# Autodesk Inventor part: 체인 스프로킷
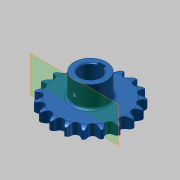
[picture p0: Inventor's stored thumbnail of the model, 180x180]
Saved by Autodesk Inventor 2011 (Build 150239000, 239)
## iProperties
Created: 2014-11
Part Number: 체인 스프로킷
Material: Steel
Document SubType Name: Modeling
Designer: KYOUNG IL JANG
Density: 7.85 g/cm^3
Mass: 738.264 g
Surface Area: 236.923 cm^2
Volume: 94.0463 cm^3
CustomPartVersion: 1
Company: 한국ATC센터
Author: KYOUNG IL JANG
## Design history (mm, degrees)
sketch "이론적 톱니 프로파일"
  geometry: L1 (0, 0)-(0, 45.567); L2 (0, 0)-(14.795, 43.098); L3 (0, 45.567)-(14.795, 43.098); L4 (0, 45.567)-(5.661, 50.015); L5 (5.661, 50.015)-(-5.141, 45.406); L6 (-12.428, 43.493)-(-5.573, 46.417); L7 (-5.141, 45.406)-(-5.573, 46.417); L8 (5.573, 46.417)-(5.141, 45.406); L9 (0, 0)-(8.138, 48.771); A1 r 45.567 centre (0, 0) between (0, 45.567) and (14.795, 43.098); A2 r 49.445 centre (0, 0) between (7.302, 48.903) and (-7.302, 48.903); A3 r 4.545 centre (0, 45.567) between (-3.574, 42.758) and (3.574, 42.758); A4 r 7.453 centre (12.428, 43.493) between (7.302, 48.903) and (5.573, 46.417); A5 r 7.453 centre (-12.428, 43.493) between (-5.573, 46.417) and (-7.302, 48.903); A6 r 11.745 centre (5.661, 50.015) between (-5.141, 45.406) and (-3.574, 42.758); A7 r 11.745 centre (-5.661, 50.015) between (3.574, 42.758) and (5.141, 45.406); 2 further points
  constraints: 18 end point, 15 point on circle, 7 centre point, 3 coincident, 3 point on line, 3 symmetric about line, 3 tangent, 1 equal radius, 1 midpoint, 1 parallel, 1 vertical, 1 other
  dimensions: "d0" = 91.13301 diameter of A1 (computed from da_p, da_z); "d2" = 18.9474 deg angle of L2 L1 (computed from da_z); "d3" = 4.545 radius of A3 (= 0.5 x da_Dr + da_SC); "d10" = 128.158 deg angle of L4 L1 (computed from da_z); "d11" = 15.0526 deg angle of L5 L4 (computed from da_z); "d12" = 7.2 distance of L3.start L4.end (= 0.8 x da_Dr); "d13" = 11.745 distance of L4.end L5.end (= 1.3 x da_Dr + da_SC); "d14" = 12.6 distance of A4.centre L1.end (= 1.4 x da_Dr); "d23" = 4.5 distance from line of L9.end L3 (= da_Ha)
sketch "톱니 프로파일"
  geometry: L1 (0, 0)-(0, 45.567); L2 (0, 45.567)-(4.203, 43.837); L3 (0, 45.567)-(-4.203, 43.837); A1 r 4.545 centre (0, 45.567) between (-4.203, 43.837) and (4.203, 43.837); A2 r 22.68 centre (25.176, 35.206) between (7.12, 48.93) and (4.203, 43.837); A3 r 22.68 centre (-25.176, 35.206) between (-4.203, 43.837) and (-7.12, 48.93); A4 r 49.445 centre (0, 0) between (-7.12, 48.93) and (7.12, 48.93) reference; 1 further point
  constraints: 9 point on circle, 6 end point, 3 centre point, 2 tangent, 1 coincident, 1 equal radius, 1 vertical, 1 other
  dimensions: "d44" = 135.263 deg angle of L3 L2 (= da_Alfa); "d45" = 22.68 radius of A2 (= da_Re); "d46" = 4.545 radius of A1 (= da_Ri)
sketch "단면 프로파일"
  geometry: L1 (49.445, 0)-(-49.445, 0) reference; L2 (33.265, 6.65)-(-33.265, 6.65); L3 (-33.265, 6.65)-(-33.265, -6.65); L4 (-33.265, -6.65)-(33.265, -6.65); L5 (33.265, -6.65)-(33.265, 6.65); L6 (33.265, 6.65)-(49.445, 6.65); L7 (49.445, 6.65)-(49.445, -6.65); L8 (49.445, -6.65)-(33.265, -6.65); L9 (33.265, -6.65)-(33.265, 6.65); L10 (42.183, 6.65)-(0, 6.65); L11 (0, 6.65)-(0, -6.65); L12 (0, -6.65)-(42.183, -6.65); L13 (0, 6.65)-(0, -6.65); L14 (49.445, 4.775)-(49.445, -4.775); A1 r 15 centre (42.183, -8.35) between (49.445, 4.775) and (42.183, 6.65); A2 r 15 centre (42.183, 8.35) between (42.183, -6.65) and (49.445, -4.775); 2 further points
  constraints: 26 end point, 7 midpoint, 5 perpendicular, 4 parallel, 4 point on circle, 3 point on line, 3 symmetric about line, 2 centre point, 2 horizontal, 2 tangent, 1 collinear, 1 other
  dimensions: "d30" = 13.3 distance between parallel lines of L8 L6 (= da_Bf); "d31" = 66.53007 distance between parallel lines of L3 L5 (= da_Ds); "d32" = 13.3 distance between parallel lines of L4 L2 (= da_Bs); "d33" = 1.875 distance from line of L14.start L6 (= da_Ba); "d34" = 15 radius of A1 (= da_Rx); "d43" = 6.65 distance between parallel lines of L4 L1 (computed from da_k, da_pt, da_Bs)
revolve "슈라우드" stored, may be unused: angle "d36" = 90 deg
revolve "스트랜드" stored, may be unused: angle "d37" = 90 deg
extrude "이론적 톱니" cut sketch "이론적 톱니 프로파일" stored distance "d18" = 10; taper "d19" = 0 deg; dims "d49" = 0, "form_type" = 0 [user parameter]
extrude "톱니" cut sketch "톱니 프로파일" stored distance "d47" = 10; taper "d48" = 0 deg; dims "d50" = 10, "form_type" = 0 [user parameter]
node "타이밍 평면"
node "작업 평면3"
sketch "스케치5"
  geometry: C1 r 20 at (0, -45.567); 1 further point
  constraints: 1 centre point, 1 coincident
  dimensions: "d52" = 40 diameter of C1
extrude "돌출4" join sketch "스케치5" stored distance "d53" = 10; taper "d54" = 0 deg
sketch "스케치6"
  geometry: L1 (4, 11.843)-(4, 16.5); L2 (4, 16.5)-(-4, 16.5); L3 (-4, 16.5)-(-4, 11.843); A1 r 12.5 centre (0, 0) between (4, 11.843) and (-4, 11.843); 1 further point
  constraints: 6 end point, 2 parallel, 2 point on circle, 1 centre point, 1 coincident, 1 perpendicular, 1 vertical
  dimensions: "d55" = 25 diameter of A1; "d56" = 29 dimension on A1 L2 (computed from d55); "d57" = 8 distance of L1.end L2.end
extrude "돌출5" cut sketch "스케치6" stored distance "d58" = 10; taper "d59" = 0 deg
fillet "모깎기2" dims "d60" = 3
chamfer "모따기1" distance "d61" = 1; stored, may be unused: second distance "d62" = 2, angle "d63" = 45 deg
node "작업 평면4"
sketch "스케치7"
  geometry: L1 (-13.5, -13.3)-(13.5, -13.3) reference; 4 further points
  constraints: 1 vertical alignment
  dimensions: "d65" = 25 distance from line of point (0, 11.7) L1
hole "구멍1" sketch "스케치7" at (0, 11.7) diameter "d66" = 5; stored, may be unused: countersink angle "d70" = 90 deg, drill point angle "d72" = 118 deg; dims "d67" = 6, "d68" = 4, "d69" = 2, "d71" = 8
feature "스레드1" dims "d73" = 10, "d74" = 0
body "Solid1"
pattern_linear "스트랜드 패턴" dims "d40" = 24 (= da_pt)
pattern_circular "톱니 패턴" dims angle "d21" = 360 deg
other parameters: "da_p" = 15 [user parameter; used in 1 equation term], "da_Dr" = 9 [user parameter; used in 4 equation terms], "da_SC" = 0.045 [user parameter; used in 2 equation terms], "da_Ha" = 4.5 [user parameter; used in 1 equation term], "da_pt" = 24 [user parameter; used in 2 equation terms], "da_Bf" = 13.3 [user parameter; used in 1 equation term], "d28" = 0, "d29" = 0, "da_Ba" = 1.875 [user parameter; used in 1 equation term], "da_Rx" = 15 [user parameter; used in 1 equation term], "da_Ra" = 0.6 [user parameter], "da_Bs" = 13.3 [user parameter; used in 2 equation terms], "da_Ds" = 66.53007 [user parameter; used in 1 equation term], "d42" = 0, "da_Re" = 22.68 [user parameter; used in 1 equation term], "da_Ri" = 4.545 [user parameter; used in 1 equation term], "da_Alfa" = 135.263 deg [user parameter; used in 1 equation term]
